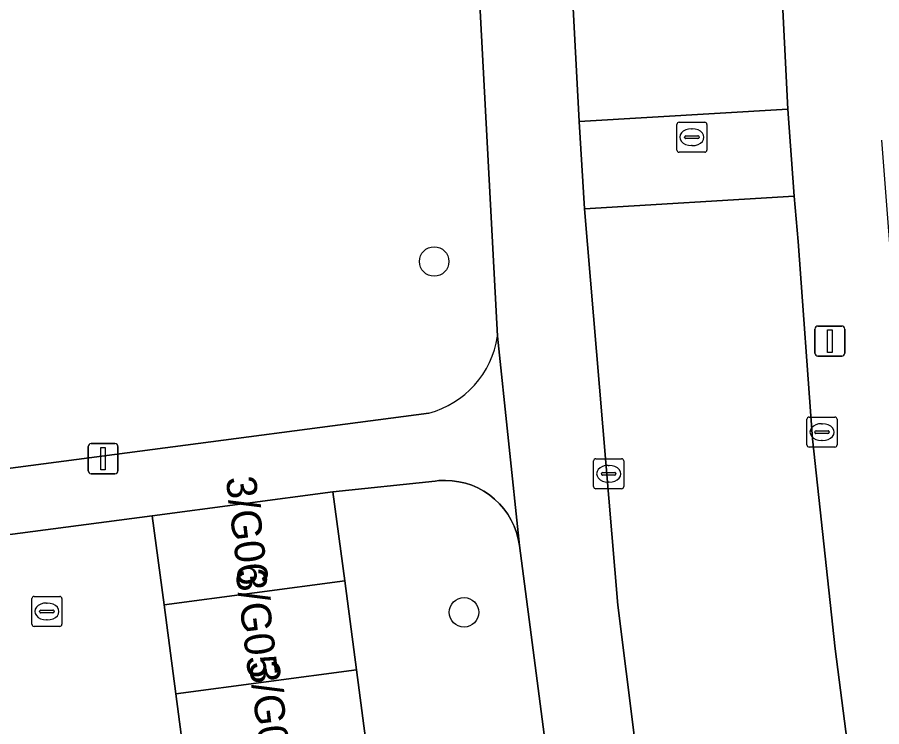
# Model space of a CAD drawing. Extents: x 161084 to 161928, y 385354 to 386522.
# Drawn here: x 161271.54 to 161300.26, y 385645.94 to 385669.53 of the extents above; entities that cross this region are included whole.
import ezdxf

# ---------------------------------------------------------------- set-up
doc = ezdxf.new("R2010")
doc.units = 0
for name, color, linetype in [('IMGEO_Boom', 7, 'Continuous'), ('IMGEO_Groenvoorziening', 7, 'Continuous'), ('IMGEO_Kolk', 7, 'Continuous'), ('IMGEO_Lichtmast', 7, 'Continuous'), ('IMGEO_Muur', 7, 'Continuous'), ('IMGEO_Pand', 7, 'Continuous'), ('IMGEO_Pand_nummerreeks', 7, 'Continuous'), ('IMGEO_Rijbaan_lokaal_open', 7, 'Continuous'), ('IMGEO_Rioolput', 7, 'Continuous'), ('IMGEO_Voetpad_open', 7, 'Continuous')]:
    doc.layers.add(name, color=color, linetype=linetype)

msp = doc.modelspace()

# ---------------------------------------------------------------- linework, layer by layer
at = {"layer": 'IMGEO_Boom'}
for centre in [(161285.388, 385661.411), (161286.382, 385649.748)]:
    msp.add_circle(centre, 0.489, dxfattribs=at)
at = {"layer": 'IMGEO_Groenvoorziening'}
for points in [[(161287.489, 385658.928), (161285.817, 385690.369)], [(161264.31, 385653.617), (161285.207, 385656.371)], [(161290.505, 385634.478), (161288.22, 385651.972), (161288.181, 385652.191), (161288.122, 385652.406), (161288.044, 385652.615), (161287.948, 385652.816), (161287.834, 385653.008), (161287.704, 385653.188), (161287.558, 385653.357), (161287.397, 385653.511), (161287.224, 385653.651), (161287.038, 385653.774), (161286.843, 385653.881), (161286.638, 385653.97), (161286.427, 385654.04), (161286.21, 385654.09), (161285.989, 385654.122), (161285.767, 385654.133), (161285.544, 385654.125), (161285.426, 385654.112), (161282.028, 385653.748), (161282.417, 385650.79), (161282.806, 385647.832), (161283.195, 385644.874)]]:
    msp.add_lwpolyline(points, dxfattribs=at)
msp.add_arc((161284.43, 385659.361), 3.089, 284.5638, 351.9415, dxfattribs=at)
at = {"layer": 'IMGEO_Kolk'}
for p, q in [((161297.849, 385656.238), (161298.701, 385656.238)), ((161297.774, 385655.312), (161297.774, 385656.164)), ((161298.262, 385656.018), (161298.287, 385656.018)), ((161298.775, 385656.164), (161298.775, 385655.312)), ((161298.033, 385655.732), (161298.033, 385655.744)), ((161298.471, 385655.695), (161298.073, 385655.695)), ((161298.076, 385655.781), (161298.474, 385655.781)), ((161298.517, 385655.744), (161298.517, 385655.732)), ((161298.285, 385655.458), (161298.26, 385655.458)), ((161298.701, 385655.238), (161297.849, 385655.238)), ((161290.762, 385654.853), (161291.614, 385654.853)), ((161290.687, 385653.927), (161290.687, 385654.779)), ((161291.175, 385654.633), (161291.2, 385654.633)), ((161291.688, 385654.779), (161291.688, 385653.927)), ((161290.946, 385654.347), (161290.946, 385654.359)), ((161291.384, 385654.31), (161290.986, 385654.31)), ((161290.989, 385654.396), (161291.387, 385654.396)), ((161291.43, 385654.359), (161291.43, 385654.347)), ((161291.198, 385654.073), (161291.173, 385654.073)), ((161291.614, 385653.853), (161290.762, 385653.853)), ((161272.097, 385650.276), (161272.949, 385650.276)), ((161272.022, 385649.35), (161272.022, 385650.202)), ((161272.51, 385650.056), (161272.535, 385650.056)), ((161273.023, 385650.202), (161273.023, 385649.35)), ((161272.281, 385649.77), (161272.281, 385649.782)), ((161272.719, 385649.733), (161272.321, 385649.733)), ((161272.324, 385649.819), (161272.722, 385649.819)), ((161272.765, 385649.782), (161272.765, 385649.77)), ((161272.533, 385649.496), (161272.508, 385649.496)), ((161272.949, 385649.276), (161272.097, 385649.276))]:
    msp.add_line(p, q, dxfattribs=at)
for points in [[(161297.849, 385656.238), (161298.701, 385656.238)], [(161297.774, 385655.312), (161297.774, 385656.164)], [(161298.775, 385656.164), (161298.775, 385655.312)], [(161298.701, 385655.238), (161297.849, 385655.238)], [(161290.762, 385654.853), (161291.614, 385654.853)], [(161290.687, 385653.927), (161290.687, 385654.779)], [(161291.688, 385654.779), (161291.688, 385653.927)], [(161291.614, 385653.853), (161290.762, 385653.853)], [(161272.097, 385650.276), (161272.949, 385650.276)], [(161272.022, 385649.35), (161272.022, 385650.202)], [(161273.023, 385650.202), (161273.023, 385649.35)], [(161272.949, 385649.276), (161272.097, 385649.276)]]:
    msp.add_lwpolyline(points, dxfattribs=at)
for centre, radius, start, end in [((161297.851, 385656.162), 0.0765, 91.552, 178.448), ((161297.851, 385656.162), 0.0765, 91.552, 178.448), ((161298.699, 385656.162), 0.0765, 1.552, 88.448), ((161298.699, 385656.162), 0.0765, 1.552, 88.448), ((161298.073, 385655.741), 0.0403, 85.8775, 175.7526), ((161298.07, 385655.731), 0.0366, 178.938, 274.7102), ((161298.474, 385655.738), 0.043, 264.8664, 352.4533), ((161298.478, 385655.743), 0.0386, 1.7309, 96.639), ((161297.851, 385655.314), 0.0765, 181.552, 268.448), ((161297.851, 385655.314), 0.0765, 181.552, 268.448), ((161298.699, 385655.314), 0.0765, 271.552, 358.448), ((161298.699, 385655.314), 0.0765, 271.552, 358.448), ((161290.764, 385654.777), 0.0765, 91.552, 178.448), ((161290.764, 385654.777), 0.0765, 91.552, 178.448), ((161291.612, 385654.777), 0.0765, 1.552, 88.448), ((161291.612, 385654.777), 0.0765, 1.552, 88.448), ((161290.986, 385654.356), 0.0403, 85.8775, 175.7526), ((161290.983, 385654.346), 0.0366, 178.938, 274.7102), ((161291.387, 385654.353), 0.043, 264.8664, 352.4533), ((161291.391, 385654.358), 0.0386, 1.7309, 96.639), ((161290.764, 385653.929), 0.0765, 181.552, 268.448), ((161290.764, 385653.929), 0.0765, 181.552, 268.448), ((161291.612, 385653.929), 0.0765, 271.552, 358.448), ((161291.612, 385653.929), 0.0765, 271.552, 358.448), ((161272.099, 385650.2), 0.0765, 91.552, 178.448), ((161272.099, 385650.2), 0.0765, 91.552, 178.448), ((161272.947, 385650.2), 0.0765, 1.552, 88.448), ((161272.947, 385650.2), 0.0765, 1.552, 88.448), ((161272.321, 385649.779), 0.0403, 85.8775, 175.7526), ((161272.318, 385649.769), 0.0366, 178.938, 274.7102), ((161272.722, 385649.776), 0.043, 264.8664, 352.4533), ((161272.726, 385649.781), 0.0386, 1.7309, 96.639), ((161272.099, 385649.352), 0.0765, 181.552, 268.448), ((161272.099, 385649.352), 0.0765, 181.552, 268.448), ((161272.947, 385649.352), 0.0765, 271.552, 358.448), ((161272.947, 385649.352), 0.0765, 271.552, 358.448)]:
    msp.add_arc(centre, radius, start, end, dxfattribs=at)
for centre, major_axis, ratio, start_param, end_param in [((161298.261, 385655.738), (-0.387, 0.002), 0.722429, 4.712389, 7.853982), ((161298.286, 385655.738), (-0.39, 0.002), 0.717154, 1.570796, 4.712389), ((161291.174, 385654.353), (-0.387, 0.002), 0.722429, 4.712389, 7.853982), ((161291.199, 385654.353), (-0.39, 0.002), 0.717154, 1.570796, 4.712389), ((161272.509, 385649.776), (-0.387, 0.002), 0.722429, 4.712389, 7.853982), ((161272.534, 385649.776), (-0.39, 0.002), 0.717154, 1.570796, 4.712389)]:
    msp.add_ellipse(centre, major_axis=major_axis, ratio=ratio, start_param=start_param, end_param=end_param, dxfattribs=at)
at = {"layer": 'IMGEO_Lichtmast'}
for p, q in [((161298.038, 385658.364), (161298.038, 385659.164)), ((161298.038, 385659.164), (161298.038, 385658.364)), ((161298.138, 385659.264), (161298.928, 385659.264)), ((161298.928, 385659.264), (161298.138, 385659.264)), ((161299.028, 385659.164), (161299.028, 385658.364)), ((161299.028, 385658.364), (161299.028, 385659.164)), ((161298.928, 385658.264), (161298.138, 385658.264)), ((161298.138, 385658.264), (161298.928, 385658.264)), ((161273.893, 385654.455), (161273.893, 385655.255)), ((161273.893, 385655.255), (161273.893, 385654.455)), ((161273.993, 385655.355), (161274.783, 385655.355)), ((161274.783, 385655.355), (161273.993, 385655.355)), ((161274.883, 385655.255), (161274.883, 385654.455)), ((161274.883, 385654.455), (161274.883, 385655.255)), ((161274.783, 385654.355), (161273.993, 385654.355)), ((161273.993, 385654.355), (161274.783, 385654.355))]:
    msp.add_line(p, q, dxfattribs=at)
for points in [[(161298.458, 385659.139), (161298.608, 385659.139), (161298.608, 385658.389), (161298.458, 385658.389), (161298.458, 385659.139)], [(161274.313, 385655.23), (161274.463, 385655.23), (161274.463, 385654.48), (161274.313, 385654.48), (161274.313, 385655.23)]]:
    msp.add_lwpolyline(points, dxfattribs=at)
for centre, start, end in [((161298.138, 385659.164), 90, 180), ((161298.138, 385659.164), 90, 180), ((161298.928, 385659.164), 0, 90), ((161298.928, 385659.164), 360, 90), ((161298.138, 385658.364), 180, 270), ((161298.138, 385658.364), 180, 270), ((161298.928, 385658.364), 270, 0), ((161298.928, 385658.364), 270, 0), ((161273.993, 385655.255), 90, 180), ((161273.993, 385655.255), 90, 180), ((161274.783, 385655.255), 0, 90), ((161274.783, 385655.255), 360, 90), ((161273.993, 385654.455), 180, 270), ((161273.993, 385654.455), 180, 270), ((161274.783, 385654.455), 270, 0), ((161274.783, 385654.455), 270, 0)]:
    msp.add_arc(centre, 0.1, start, end, dxfattribs=at)
at = {"layer": 'IMGEO_Muur'}
msp.add_lwpolyline([(161268.082, 385651.914), (161276.025, 385652.959)], dxfattribs=at)
at = {"layer": 'IMGEO_Pand'}
for points in [[(161282.028, 385653.748), (161276.025, 385652.959), (161276.414, 385650.001), (161282.417, 385650.79)], [(161282.417, 385650.79), (161276.414, 385650.001), (161276.803, 385647.043), (161282.806, 385647.832)], [(161282.806, 385647.832), (161276.803, 385647.043), (161277.192, 385644.084), (161283.195, 385644.874)]]:
    msp.add_lwpolyline(points, close=True, dxfattribs=at)
at = {"layer": 'IMGEO_Rijbaan_lokaal_open'}
for points in [[(161286.969, 385729.53), (161287.862, 385710.445), (161288.659, 385695.346), (161290.207, 385666.069), (161297.135, 385666.475), (161293.907, 385730.889)], [(161300.404, 385635.389), (161298.709, 385648.536), (161297.96, 385655.516), (161297.477, 385662.072), (161297.348, 385663.583), (161290.388, 385663.165), (161291.495, 385649.984), (161293.715, 385632.256)]]:
    msp.add_lwpolyline(points, dxfattribs=at)
for points in [[(161297.135, 385666.475), (161290.207, 385666.069), (161290.388, 385663.165), (161297.348, 385663.583)], [(161281.626, 385632.587), (161281.231, 385635.587), (161278.357, 385635.22), (161277.969, 385638.168), (161277.581, 385641.126), (161277.192, 385644.084), (161276.803, 385647.043), (161276.414, 385650.001), (161276.025, 385652.959), (161268.082, 385651.914), (161268.453, 385649.1), (161268.847, 385646.11), (161269.241, 385643.121), (161269.635, 385640.132), (161270.029, 385637.142), (161270.423, 385634.153), (161270.817, 385631.163)]]:
    msp.add_lwpolyline(points, close=True, dxfattribs=at)
at = {"layer": 'IMGEO_Rioolput'}
for p, q in [((161293.525, 385666.042), (161294.377, 385666.042)), ((161293.45, 385665.116), (161293.45, 385665.968)), ((161293.938, 385665.822), (161293.963, 385665.822)), ((161294.451, 385665.968), (161294.451, 385665.116)), ((161293.709, 385665.536), (161293.709, 385665.548)), ((161294.147, 385665.499), (161293.749, 385665.499)), ((161293.752, 385665.585), (161294.15, 385665.585)), ((161294.193, 385665.548), (161294.193, 385665.536)), ((161293.961, 385665.262), (161293.936, 385665.262)), ((161294.377, 385665.042), (161293.525, 385665.042))]:
    msp.add_line(p, q, dxfattribs=at)
for points in [[(161293.525, 385666.042), (161294.377, 385666.042)], [(161293.45, 385665.116), (161293.45, 385665.968)], [(161294.451, 385665.968), (161294.451, 385665.116)], [(161294.377, 385665.042), (161293.525, 385665.042)]]:
    msp.add_lwpolyline(points, dxfattribs=at)
for centre, radius, start, end in [((161293.527, 385665.966), 0.0765, 91.552, 178.448), ((161293.527, 385665.966), 0.0765, 91.552, 178.448), ((161294.375, 385665.966), 0.0765, 1.552, 88.448), ((161294.375, 385665.966), 0.0765, 1.552, 88.448), ((161293.749, 385665.545), 0.0403, 85.8775, 175.7526), ((161293.746, 385665.535), 0.0366, 178.938, 274.7102), ((161294.15, 385665.542), 0.043, 264.8664, 352.4533), ((161294.154, 385665.547), 0.0386, 1.7309, 96.639), ((161293.527, 385665.118), 0.0765, 181.552, 268.448), ((161293.527, 385665.118), 0.0765, 181.552, 268.448), ((161294.375, 385665.118), 0.0765, 271.552, 358.448), ((161294.375, 385665.118), 0.0765, 271.552, 358.448)]:
    msp.add_arc(centre, radius, start, end, dxfattribs=at)
for centre, major_axis, ratio, start_param, end_param in [((161293.937, 385665.542), (-0.387, 0.002), 0.722429, 4.712389, 7.853982), ((161293.962, 385665.542), (-0.39, 0.002), 0.717154, 1.570796, 4.712389)]:
    msp.add_ellipse(centre, major_axis=major_axis, ratio=ratio, start_param=start_param, end_param=end_param, dxfattribs=at)
at = {"layer": 'IMGEO_Voetpad_open'}
for points in [[(161293.907, 385730.889), (161297.135, 385666.475), (161297.348, 385663.583), (161297.477, 385662.072), (161297.96, 385655.516), (161298.709, 385648.536), (161300.404, 385635.389), (161302.494, 385619.451), (161305.617, 385619.727), (161305.114, 385623.524), (161303.721, 385632.139), (161301.19, 385653.36), (161300.263, 385665.439)], [(161287.54, 385698.024), (161285.817, 385690.369), (161287.489, 385658.928), (161288.22, 385651.972), (161290.505, 385634.478), (161291.477, 385627.041), (161291.897, 385627.389), (161292.285, 385627.774), (161292.636, 385628.191), (161292.949, 385628.638), (161293.221, 385629.112), (161293.449, 385629.608), (161293.632, 385630.122)], [(161293.715, 385632.256), (161291.495, 385649.984), (161290.388, 385663.165), (161290.207, 385666.069), (161288.659, 385695.346)], [(161285.426, 385654.112), (161285.544, 385654.125), (161285.767, 385654.133), (161285.989, 385654.122), (161286.21, 385654.09), (161286.427, 385654.04), (161286.638, 385653.97), (161286.843, 385653.881), (161287.038, 385653.774), (161287.224, 385653.651), (161287.397, 385653.511), (161287.558, 385653.357), (161287.704, 385653.188), (161287.834, 385653.008), (161287.948, 385652.816), (161288.044, 385652.615), (161288.122, 385652.406), (161288.181, 385652.191), (161288.22, 385651.972), (161287.489, 385658.928)], [(161285.207, 385656.371), (161264.31, 385653.617)], [(161261.478, 385655.239), (161262.101, 385651.304), (161268.059, 385652.09), (161268.082, 385651.914), (161276.025, 385652.959), (161282.028, 385653.748), (161285.426, 385654.112)]]:
    msp.add_lwpolyline(points, dxfattribs=at)
msp.add_arc((161284.43, 385659.361), 3.089, 284.5638, 351.9415, dxfattribs=at)

# ---------------------------------------------------------------- texts
at = {"layer": 'IMGEO_Pand_nummerreeks'}
for s, p in [('3/G06', (161278.464, 385654.217)), ('3/G05', (161278.788, 385651.141)), ('3/G04', (161279.234, 385648.077))]:
    msp.add_text(s, height=1, rotation=276.8743, dxfattribs=at).set_placement(p)

doc.saveas('drawing.dxf')
